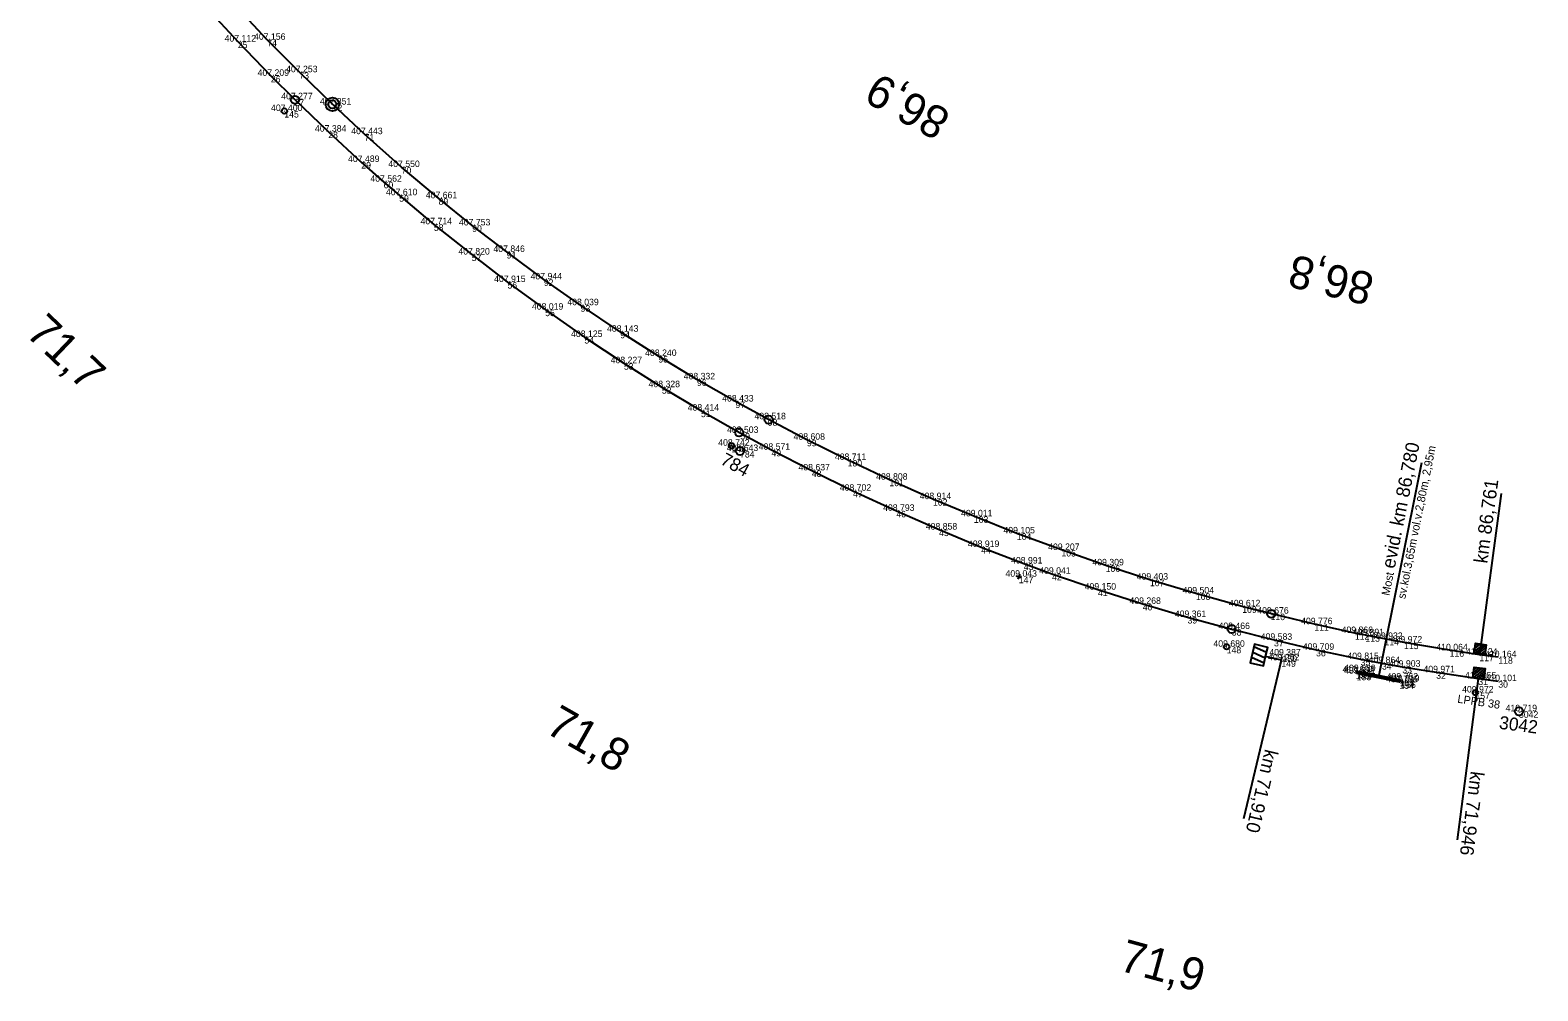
# Model space of a CAD drawing. Extents: x -663503 to -663109, y -1005607 to -1005191.
# Drawn here: x -663387.5 to -663109.1, y -1005606.9 to -1005429.6 of the extents above; entities that cross this region are included whole.
import ezdxf

# ---------------------------------------------------------------- set-up
doc = ezdxf.new("R2010")
doc.units = 0
for name, color, linetype in [('Vrstva 1', 7, 'Continuous'), ('Vrstva 17', 7, 'Continuous'), ('Vrstva 18', 7, 'Continuous'), ('Vrstva 23', 7, 'Continuous'), ('Vrstva 27', 7, 'Continuous'), ('Vrstva 3', 7, 'Continuous'), ('Vrstva 60', 7, 'Continuous'), ('Vrstva 61', 7, 'Continuous'), ('Vrstva 63', 7, 'Continuous'), ('Vrstva 7', 7, 'Continuous')]:
    doc.layers.add(name, color=color, linetype=linetype)

msp = doc.modelspace()

# ---------------------------------------------------------------- linework, layer by layer
at = {"layer": 'Vrstva 1'}
for points in [[(-663354.73, -1005425.68), (-663349.15, -1005431.73), (-663343.05, -1005438.05), (-663338.69, -1005442.38), (-663332.46, -1005448.35), (-663326.35, -1005453.95), (-663322.24, -1005457.59), (-663319.36, -1005460.08), (-663312.96, -1005465.45), (-663305.98, -1005471.03), (-663299.37, -1005476.1), (-663292.41, -1005481.19), (-663285.17, -1005486.24), (-663277.87, -1005491.08), (-663270.86, -1005495.5), (-663263.65, -1005499.83), (-663256.39, -1005503.94), (-663250.63, -1005507.05), (-663243.19, -1005510.86), (-663235.58, -1005514.6), (-663227.57, -1005518.32), (-663219.69, -1005521.78), (-663211.91, -1005524.99), (-663204.05, -1005528.04), (-663198.84, -1005529.94), (-663190.36, -1005532.86), (-663182.08, -1005535.49), (-663173.81, -1005537.91), (-663165.65, -1005540.13), (-663157.85, -1005542.12), (-663150.09, -1005543.96), (-663141.86, -1005545.67), (-663137.93, -1005546.41), (-663134.17, -1005547.08), (-663127.91, -1005548.11), (-663120.14, -1005549.26), (-663116.45, -1005549.74)], [(-663116.44, -1005545.33), (-663119.94, -1005544.86), (-663125.43, -1005544.05), (-663133.85, -1005542.63), (-663137.45, -1005541.96), (-663140.98, -1005541.27), (-663142.92, -1005540.87), (-663150.4, -1005539.24), (-663158.49, -1005537.29), (-663163.72, -1005535.94), (-663172.28, -1005533.56), (-663180.76, -1005531.02), (-663188.92, -1005528.38), (-663197.09, -1005525.54), (-663205.34, -1005522.48), (-663213.27, -1005519.33), (-663220.81, -1005516.16), (-663228.86, -1005512.57), (-663236.57, -1005508.93), (-663244.09, -1005505.2), (-663251.32, -1005501.42), (-663257.28, -1005498.15), (-663264.39, -1005494.06), (-663271.5, -1005489.75), (-663278.54, -1005485.27), (-663285.86, -1005480.38), (-663292.65, -1005475.61), (-663299.51, -1005470.55), (-663305.88, -1005465.65), (-663312.09, -1005460.64), (-663318.91, -1005454.88), (-663325.76, -1005448.81), (-663331.64, -1005443.35), (-663337.79, -1005437.39), (-663343.71, -1005431.4), (-663349.66, -1005425.07)]]:
    msp.add_lwpolyline(points, dxfattribs=at)
at = {"layer": 'Vrstva 17'}
msp.add_line((-663142.75, -1005548.16), (-663134.35, -1005549.81), dxfattribs=at)
at = {"layer": 'Vrstva 18'}
msp.add_line((-663130.64, -1005509.46), (-663138.53, -1005548.68), dxfattribs=at)
msp.add_lwpolyline([(-663142.58, -1005548.36), (-663142.45, -1005547.89), (-663134.6, -1005549.46), (-663134.69, -1005549.95), (-663142.58, -1005548.36)], dxfattribs=at)
at = {"layer": 'Vrstva 23'}
msp.add_line((-663156.27, -1005545.01), (-663156.27, -1005545.01), dxfattribs=at)
at = {"layer": 'Vrstva 27'}
msp.add_line((-663120.72, -1005551.83), (-663120.62, -1005551.85), dxfattribs=at)
msp.add_circle((-663120.67, -1005551.84), 0.5, dxfattribs=at)
at = {"layer": 'Vrstva 3'}
for p, q in [((-663115.94, -1005515.13), (-663119.94, -1005544.86)), ((-663118.67, -1005543.02), (-663120.93, -1005544.72)), ((-663119.19, -1005542.95), (-663120.85, -1005544.19)), ((-663119.72, -1005542.87), (-663120.78, -1005543.67)), ((-663120.24, -1005542.8), (-663120.7, -1005543.14)), ((-663118.74, -1005543.54), (-663120.4, -1005544.79)), ((-663118.82, -1005544.07), (-663119.88, -1005544.87)), ((-663118.89, -1005544.6), (-663119.35, -1005544.94)), ((-663120.14, -1005549.26), (-663124.06, -1005579)), ((-663118.89, -1005547.41), (-663121.14, -1005549.13)), ((-663119.42, -1005547.34), (-663121.07, -1005548.6)), ((-663119.94, -1005547.27), (-663121, -1005548.08)), ((-663120.47, -1005547.2), (-663120.93, -1005547.55)), ((-663118.96, -1005547.93), (-663120.61, -1005549.2)), ((-663119.03, -1005548.46), (-663120.08, -1005549.27)), ((-663119.1, -1005548.98), (-663119.56, -1005549.34))]:
    msp.add_line(p, q, dxfattribs=at)
for points in [[(-663118.95, -1005545), (-663120.93, -1005544.72), (-663120.65, -1005542.74), (-663118.67, -1005543.02)], [(-663119.15, -1005549.39), (-663121.14, -1005549.13), (-663120.87, -1005547.15), (-663118.89, -1005547.41)]]:
    msp.add_lwpolyline(points, close=True, dxfattribs=at)
at = {"layer": 'Vrstva 60'}
for p, q in [((-663349.15, -1005431.73), (-663349.15, -1005431.73)), ((-663343.71, -1005431.4), (-663343.71, -1005431.4)), ((-663343.05, -1005438.05), (-663343.05, -1005438.05)), ((-663337.79, -1005437.39), (-663337.79, -1005437.39)), ((-663338.69, -1005442.38), (-663338.69, -1005442.38)), ((-663331.64, -1005443.35), (-663331.64, -1005443.35)), ((-663340.57, -1005444.54), (-663340.57, -1005444.54)), ((-663332.46, -1005448.35), (-663332.46, -1005448.35)), ((-663325.76, -1005448.81), (-663325.76, -1005448.81)), ((-663326.35, -1005453.95), (-663326.35, -1005453.95)), ((-663318.91, -1005454.88), (-663318.91, -1005454.88)), ((-663322.24, -1005457.59), (-663322.24, -1005457.59)), ((-663319.36, -1005460.08), (-663319.36, -1005460.08)), ((-663312.09, -1005460.64), (-663312.09, -1005460.64)), ((-663312.96, -1005465.45), (-663312.96, -1005465.45)), ((-663305.88, -1005465.65), (-663305.88, -1005465.65)), ((-663305.98, -1005471.03), (-663305.98, -1005471.03)), ((-663299.51, -1005470.55), (-663299.51, -1005470.55)), ((-663299.37, -1005476.1), (-663299.37, -1005476.1)), ((-663292.65, -1005475.61), (-663292.65, -1005475.61)), ((-663292.41, -1005481.19), (-663292.41, -1005481.19)), ((-663285.86, -1005480.38), (-663285.86, -1005480.38)), ((-663278.54, -1005485.27), (-663278.54, -1005485.27)), ((-663285.17, -1005486.24), (-663285.17, -1005486.24)), ((-663277.87, -1005491.08), (-663277.87, -1005491.08)), ((-663271.5, -1005489.75), (-663271.5, -1005489.75)), ((-663264.39, -1005494.06), (-663264.39, -1005494.06)), ((-663270.86, -1005495.5), (-663270.86, -1005495.5)), ((-663257.28, -1005498.15), (-663257.28, -1005498.15)), ((-663263.65, -1005499.83), (-663263.65, -1005499.83)), ((-663251.32, -1005501.42), (-663251.32, -1005501.42)), ((-663256.39, -1005503.94), (-663256.39, -1005503.94)), ((-663244.09, -1005505.2), (-663244.09, -1005505.2)), ((-663258.01, -1005506.3), (-663258.01, -1005506.3)), ((-663256.43, -1005507.28), (-663256.43, -1005507.28)), ((-663250.63, -1005507.05), (-663250.63, -1005507.05)), ((-663243.19, -1005510.86), (-663243.19, -1005510.86)), ((-663236.57, -1005508.93), (-663236.57, -1005508.93)), ((-663228.86, -1005512.57), (-663228.86, -1005512.57)), ((-663235.58, -1005514.6), (-663235.58, -1005514.6)), ((-663220.81, -1005516.16), (-663220.81, -1005516.16)), ((-663227.57, -1005518.32), (-663227.57, -1005518.32)), ((-663219.69, -1005521.78), (-663219.69, -1005521.78)), ((-663213.27, -1005519.33), (-663213.27, -1005519.33)), ((-663205.34, -1005522.48), (-663205.34, -1005522.48)), ((-663211.91, -1005524.99), (-663211.91, -1005524.99)), ((-663197.09, -1005525.54), (-663197.09, -1005525.54)), ((-663204.05, -1005528.04), (-663204.05, -1005528.04)), ((-663198.84, -1005529.94), (-663198.84, -1005529.94)), ((-663188.92, -1005528.38), (-663188.92, -1005528.38)), ((-663204.97, -1005530.47), (-663204.97, -1005530.47)), ((-663190.36, -1005532.86), (-663190.36, -1005532.86)), ((-663180.76, -1005531.02), (-663180.76, -1005531.02)), ((-663182.08, -1005535.49), (-663182.08, -1005535.49)), ((-663172.28, -1005533.56), (-663172.28, -1005533.56)), ((-663173.81, -1005537.91), (-663173.81, -1005537.91)), ((-663163.72, -1005535.94), (-663163.72, -1005535.94)), ((-663158.49, -1005537.29), (-663158.49, -1005537.29)), ((-663165.65, -1005540.13), (-663165.65, -1005540.13)), ((-663150.4, -1005539.24), (-663150.4, -1005539.24)), ((-663142.92, -1005540.87), (-663142.92, -1005540.87)), ((-663140.98, -1005541.27), (-663140.98, -1005541.27)), ((-663166.59, -1005543.4), (-663166.59, -1005543.4)), ((-663157.85, -1005542.12), (-663157.85, -1005542.12)), ((-663150.09, -1005543.96), (-663150.09, -1005543.96)), ((-663137.45, -1005541.96), (-663137.45, -1005541.96)), ((-663133.85, -1005542.63), (-663133.85, -1005542.63)), ((-663125.43, -1005544.05), (-663125.43, -1005544.05)), ((-663156.5, -1005545.9), (-663156.5, -1005545.9)), ((-663141.86, -1005545.67), (-663141.86, -1005545.67)), ((-663137.93, -1005546.41), (-663137.93, -1005546.41)), ((-663119.94, -1005544.86), (-663119.94, -1005544.86)), ((-663116.44, -1005545.33), (-663116.44, -1005545.33)), ((-663142.75, -1005548.16), (-663142.75, -1005548.16)), ((-663142.58, -1005548.36), (-663142.58, -1005548.36)), ((-663142.45, -1005547.89), (-663142.45, -1005547.89)), ((-663134.6, -1005549.46), (-663134.6, -1005549.46)), ((-663134.35, -1005549.81), (-663134.35, -1005549.81)), ((-663134.17, -1005547.08), (-663134.17, -1005547.08)), ((-663127.91, -1005548.11), (-663127.91, -1005548.11)), ((-663120.14, -1005549.26), (-663120.14, -1005549.26)), ((-663116.45, -1005549.74), (-663116.45, -1005549.74)), ((-663134.69, -1005549.95), (-663134.69, -1005549.95)), ((-663120.67, -1005551.84), (-663120.67, -1005551.84)), ((-663112.63, -1005555.3), (-663112.63, -1005555.3))]:
    msp.add_line(p, q, dxfattribs=at)
at = {"layer": 'Vrstva 63'}
for p, q in [((-663256.48, -1005507.26), (-663256.39, -1005507.31)), ((-663112.68, -1005555.29), (-663112.58, -1005555.31))]:
    msp.add_line(p, q, dxfattribs=at)
for centre in [(-663256.43, -1005507.28), (-663112.63, -1005555.3)]:
    msp.add_circle(centre, 0.756, dxfattribs=at)
at = {"layer": 'Vrstva 7'}
for p, q in [((-663340.61, -1005444.51), (-663340.54, -1005444.57)), ((-663258.05, -1005506.27), (-663257.97, -1005506.32)), ((-663205.44, -1005530.3), (-663204.5, -1005530.64)), ((-663204.79, -1005530), (-663205.14, -1005530.94)), ((-663166.64, -1005543.39), (-663166.54, -1005543.41)), ((-663159.24, -1005544.48), (-663161.56, -1005543.42)), ((-663163.41, -1005575.09), (-663156.5, -1005545.9)), ((-663159.7, -1005546.43), (-663162.02, -1005545.36)), ((-663161.79, -1005544.39), (-663159.47, -1005545.45)), ((-663156.67, -1005546.63), (-663156.32, -1005545.17))]:
    msp.add_line(p, q, dxfattribs=at)
msp.add_lwpolyline([(-663156.5, -1005545.9), (-663159.42, -1005545.21), (-663159.01, -1005543.51), (-663161.45, -1005542.93), (-663162.25, -1005546.34), (-663159.82, -1005546.91), (-663159.42, -1005545.21)], dxfattribs=at)
for centre, radius in [((-663340.57, -1005444.54), 0.5), ((-663338.6, -1005442.48), 0.75), ((-663331.69, -1005443.3), 1.25), ((-663331.69, -1005443.3), 0.752), ((-663251.16, -1005501.5), 0.75), ((-663256.61, -1005503.82), 0.75), ((-663258.01, -1005506.3), 0.5), ((-663158.36, -1005537.32), 0.75), ((-663165.69, -1005540.12), 0.75), ((-663166.59, -1005543.4), 0.5)]:
    msp.add_circle(centre, radius, dxfattribs=at)

# ---------------------------------------------------------------- texts
at = {"layer": 'Vrstva 18'}
for s, height, p in [('evid. km 86,780', 2.5, (-663135.59, -1005529.1)), ('sv.kol.3,65m vol.v.2,80m, 2,95m', 1.5, (-663133.63, -1005534.65)), ('Most', 1.5, (-663136.57, -1005534.06))]:
    msp.add_text(s, height=height, rotation=78.6368, dxfattribs=at).set_placement(p)
at = {"layer": 'Vrstva 27'}
msp.add_text('LPPB 38', height=1.5, rotation=351.6086, dxfattribs=at).set_placement((-663124.06, -1005553.71))
at = {"layer": 'Vrstva 3'}
for s, rotation, p in [('km 86,761', 82.3474, (-663118.49, -1005528.11)), ('km 71,946', 262.5009, (-663121.52, -1005566.27))]:
    msp.add_text(s, height=2.5, rotation=rotation, dxfattribs=at).set_placement(p)
at = {"layer": 'Vrstva 60'}
for s, p in [('25', (-663349.15, -1005432.93)), ('74', (-663343.71, -1005432.6)), ('26', (-663343.05, -1005439.25)), ('73', (-663337.79, -1005438.59)), ('27', (-663338.69, -1005443.58)), ('72', (-663331.64, -1005444.55)), ('145', (-663340.57, -1005445.74)), ('28', (-663332.46, -1005449.55)), ('71', (-663325.76, -1005450.01)), ('29', (-663326.35, -1005455.15)), ('70', (-663318.91, -1005456.08)), ('60', (-663322.24, -1005458.79)), ('59', (-663319.36, -1005461.28)), ('89', (-663312.09, -1005461.84)), ('58', (-663312.96, -1005466.65)), ('90', (-663305.88, -1005466.84)), ('57', (-663305.98, -1005472.23)), ('91', (-663299.51, -1005471.75)), ('56', (-663299.37, -1005477.3)), ('92', (-663292.65, -1005476.81)), ('55', (-663292.41, -1005482.39)), ('93', (-663285.86, -1005481.58)), ('94', (-663278.54, -1005486.47)), ('54', (-663285.17, -1005487.44)), ('53', (-663277.87, -1005492.28)), ('95', (-663271.5, -1005490.95)), ('96', (-663264.39, -1005495.26)), ('52', (-663270.86, -1005496.7)), ('97', (-663257.28, -1005499.35)), ('51', (-663263.65, -1005501.03)), ('98', (-663251.32, -1005502.62)), ('50', (-663256.39, -1005505.14)), ('99', (-663244.09, -1005506.4)), ('146', (-663258.01, -1005507.5)), ('784', (-663256.43, -1005508.48)), ('49', (-663250.63, -1005508.25)), ('48', (-663243.19, -1005512.06)), ('100', (-663236.57, -1005510.13)), ('101', (-663228.86, -1005513.77)), ('47', (-663235.58, -1005515.8)), ('102', (-663220.81, -1005517.35)), ('46', (-663227.57, -1005519.52)), ('45', (-663219.69, -1005522.98)), ('103', (-663213.27, -1005520.53)), ('104', (-663205.34, -1005523.68)), ('44', (-663211.91, -1005526.2)), ('105', (-663197.09, -1005526.74)), ('43', (-663204.05, -1005529.24)), ('42', (-663198.84, -1005531.14)), ('106', (-663188.92, -1005529.58)), ('147', (-663204.97, -1005531.67)), ('41', (-663190.36, -1005534.06)), ('107', (-663180.76, -1005532.22)), ('40', (-663182.08, -1005536.69)), ('108', (-663172.28, -1005534.76)), ('109', (-663163.72, -1005537.14)), ('39', (-663173.81, -1005539.11)), ('110', (-663158.49, -1005538.49)), ('38', (-663165.65, -1005541.33)), ('111', (-663150.4, -1005540.44)), ('112', (-663142.92, -1005542.07)), ('113', (-663140.98, -1005542.46)), ('148', (-663166.59, -1005544.6)), ('37', (-663157.85, -1005543.33)), ('36', (-663150.09, -1005545.16)), ('114', (-663137.45, -1005543.16)), ('115', (-663133.85, -1005543.83)), ('116', (-663125.43, -1005545.25)), ('149', (-663156.5, -1005547.1)), ('150', (-663156.27, -1005546.21)), ('35', (-663141.86, -1005546.87)), ('34', (-663137.93, -1005547.61)), ('33', (-663134.17, -1005548.28)), ('117', (-663119.94, -1005546.06)), ('118', (-663116.44, -1005546.53)), ('151', (-663142.75, -1005549.36)), ('153', (-663142.58, -1005549.57)), ('152', (-663142.45, -1005549.09)), ('155', (-663134.6, -1005550.67)), ('156', (-663134.35, -1005551.01)), ('32', (-663127.91, -1005549.31)), ('31', (-663120.14, -1005550.46)), ('30', (-663116.45, -1005550.95)), ('154', (-663134.69, -1005551.15)), ('157', (-663120.67, -1005553.04)), ('3042', (-663112.63, -1005556.5))]:
    msp.add_text(s, height=1.2, dxfattribs=at).set_placement(p)
at = {"layer": 'Vrstva 61'}
for s, p in [('407.112', (-663351.59, -1005431.73)), ('407.156', (-663346.16, -1005431.4)), ('407.209', (-663345.5, -1005438.05)), ('407.253', (-663340.24, -1005437.39)), ('407.277', (-663341.14, -1005442.38)), ('407.400', (-663343.02, -1005444.54)), ('407.351', (-663334, -1005443.35)), ('407.384', (-663334.91, -1005448.35)), ('407.443', (-663328.21, -1005448.81)), ('407.489', (-663328.8, -1005453.95)), ('407.550', (-663321.36, -1005454.88)), ('407.562', (-663324.68, -1005457.59)), ('407.610', (-663321.81, -1005460.08)), ('407.661', (-663314.45, -1005460.64)), ('407.714', (-663315.41, -1005465.45)), ('407.753', (-663308.33, -1005465.65)), ('407.820', (-663308.43, -1005471.03)), ('407.846', (-663301.96, -1005470.55)), ('407.944', (-663295.1, -1005475.61)), ('407.915', (-663301.83, -1005476.1)), ('408.019', (-663294.86, -1005481.19)), ('408.039', (-663288.32, -1005480.38)), ('408.125', (-663287.63, -1005486.24)), ('408.143', (-663281, -1005485.27)), ('408.240', (-663273.95, -1005489.75)), ('408.227', (-663280.32, -1005491.08)), ('408.332', (-663266.84, -1005494.06)), ('408.328', (-663273.32, -1005495.5)), ('408.433', (-663259.73, -1005498.15)), ('408.414', (-663266.1, -1005499.83)), ('408.518', (-663253.77, -1005501.42)), ('408.742', (-663260.46, -1005506.3)), ('408.503', (-663258.84, -1005503.94)), ('408.608', (-663246.55, -1005505.2)), ('408.643', (-663258.88, -1005507.28)), ('408.571', (-663252.99, -1005507.05)), ('408.711', (-663238.93, -1005508.93)), ('408.637', (-663245.64, -1005510.86)), ('408.702', (-663238.02, -1005514.6)), ('408.808', (-663231.31, -1005512.57)), ('408.914', (-663223.26, -1005516.16)), ('408.793', (-663230.02, -1005518.32)), ('409.011', (-663215.63, -1005519.33)), ('408.858', (-663222.14, -1005521.78)), ('409.105', (-663207.8, -1005522.48)), ('408.919', (-663214.36, -1005524.99)), ('409.207', (-663199.55, -1005525.54)), ('408.991', (-663206.4, -1005528.04)), ('409.309', (-663191.38, -1005528.38)), ('409.043', (-663207.42, -1005530.47)), ('409.041', (-663201.2, -1005529.94)), ('409.403', (-663183.21, -1005531.02)), ('409.150', (-663192.81, -1005532.86)), ('409.504', (-663174.73, -1005533.56)), ('409.268', (-663184.54, -1005535.49)), ('409.612', (-663166.17, -1005535.94)), ('409.361', (-663176.17, -1005537.91)), ('409.676', (-663160.94, -1005537.29)), ('409.776', (-663152.85, -1005539.24)), ('409.466', (-663168.1, -1005540.13)), ('409.583', (-663160.3, -1005542.12)), ('409.866', (-663145.37, -1005540.87)), ('409.891', (-663143.34, -1005541.27)), ('409.932', (-663139.9, -1005541.96)), ('409.972', (-663136.3, -1005542.63)), ('409.680', (-663169.04, -1005543.4)), ('409.387', (-663158.72, -1005545.01)), ('409.709', (-663152.54, -1005543.96)), ('410.064', (-663127.88, -1005544.05)), ('410.124', (-663122.39, -1005544.86)), ('410.164', (-663118.89, -1005545.33)), ('409.262', (-663158.95, -1005545.9)), ('410.697', (-663145.2, -1005548.16)), ('409.630', (-663144.9, -1005547.89)), ('409.815', (-663144.31, -1005545.67)), ('409.864', (-663140.38, -1005546.41)), ('409.903', (-663136.62, -1005547.08)), ('409.971', (-663130.26, -1005548.11)), ('409.631', (-663144.93, -1005548.36)), ('409.736', (-663137.14, -1005549.95)), ('409.762', (-663137.05, -1005549.46)), ('410.819', (-663136.81, -1005549.81)), ('410.055', (-663122.6, -1005549.26)), ('410.101', (-663118.81, -1005549.74)), ('409.972', (-663123.12, -1005551.84)), ('410.719', (-663115.09, -1005555.3))]:
    msp.add_text(s, height=1.2, dxfattribs=at).set_placement(p)
at = {"layer": 'Vrstva 63'}
for s, rotation, p in [('784', 331.6809, (-663260.23, -1005509.58)), ('3042', 352.5009, (-663116.4, -1005558.51))]:
    msp.add_text(s, height=2.4, rotation=rotation, dxfattribs=at).set_placement(p)
at = {"layer": 'Vrstva 7'}
for s, height, rotation, p in [('86,9', 6, 151.2557, (-663217.24, -1005444.87)), ('86,8', 6, 166.4526, (-663139.07, -1005474.65)), ('71,7', 6, 316.2547, (-663388.52, -1005485.79)), ('71,8', 6, 330.4281, (-663292.62, -1005559.1)), ('km 71,910', 2.5, 256.6751, (-663159.5, -1005562.18)), ('71,9', 6, 344.7722, (-663186.67, -1005603.07))]:
    msp.add_text(s, height=height, rotation=rotation, dxfattribs=at).set_placement(p)

doc.saveas('drawing.dxf')
